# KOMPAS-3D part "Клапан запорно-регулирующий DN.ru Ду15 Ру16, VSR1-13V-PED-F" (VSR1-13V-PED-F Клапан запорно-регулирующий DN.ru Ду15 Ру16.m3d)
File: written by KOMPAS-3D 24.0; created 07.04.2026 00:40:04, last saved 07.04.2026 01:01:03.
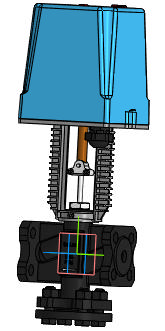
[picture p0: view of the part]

Document properties: Автор: R2D2; Полное имя файла: VSR1-13V-PED-F Клапан запорно-регулирующий DN.ru Ду15 Ру16.cdw

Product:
- Part/product: Клапан запорно-регулирующий DN.ru Ду15 Ру16  | designation VSR1-13V-PED-F
    Масса: 6.1
    Раздел спецификации: Прочие изделия
    Форматы листов документа: A3
    Примечание: D090-02885

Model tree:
1. Операция без истории:1  (labels: SHAPEOBJECT3D_ATTR_BUTT)

Expressions: VSR1-13V-PED-F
